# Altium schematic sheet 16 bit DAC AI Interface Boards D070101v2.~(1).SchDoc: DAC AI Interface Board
size B; Engineer: J. Heefner; DocumentNumber: D070101; Revision: 01; SheetNumber: 1; SheetTotal: 1; PageSetup: Record=PageOptions¦CenterHorizontal=True¦CenterVertical=True¦PrintScale=1.12¦XCorrection=1.00¦YCorrection=1.00¦PrintKind=0¦BorderSize=5000000¦LeftOffset=0¦BottomOffset=0¦Orientation=2¦PaperLength=1000¦PaperWidth=1000¦Scale=100¦PaperSource=15¦PrintQuality=1200¦MediaType=1¦DitherType=10¦PaperKind=Tabloid¦PrintScaleMode=1
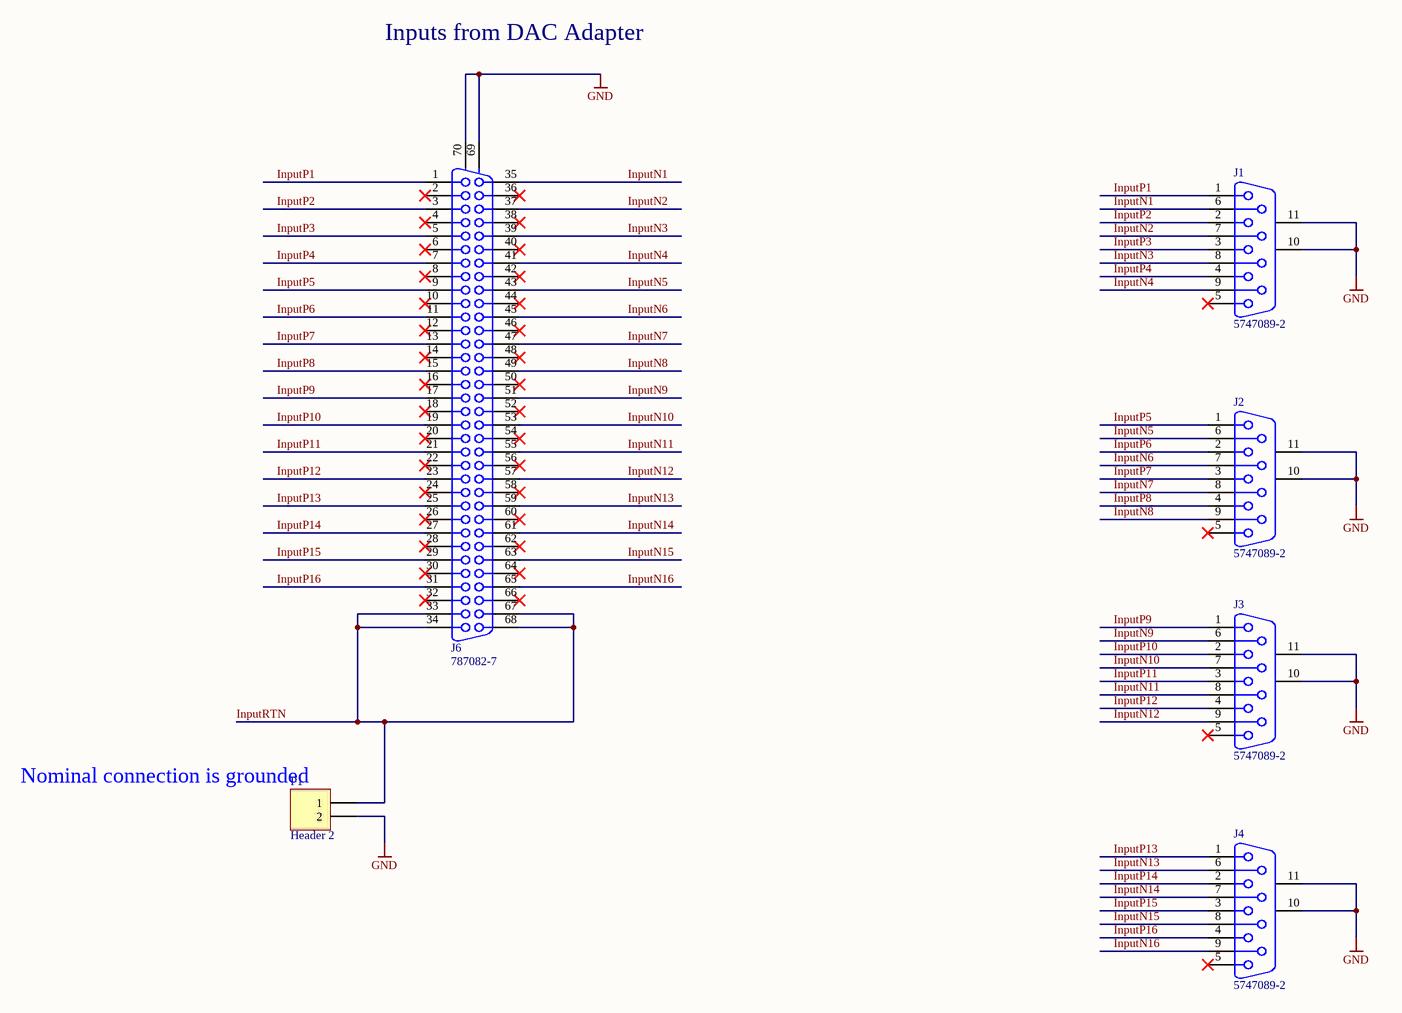
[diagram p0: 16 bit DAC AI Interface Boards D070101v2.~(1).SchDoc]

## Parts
J1  5747089-2  [DB9/F]
J2  5747089-2  [DB9/F]
J3  5747089-2  [DB9/F]
J4  5747089-2  [DB9/F]
J6  787082-7  [787082-7]
P1  Header 2  [HDR1X2]

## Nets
GND: J1.10(MH1) J1.11(MH2) J2.10(MH1) J2.11(MH2) J3.10(MH1) J3.11(MH2) J4.10(MH1) J4.11(MH2) J6.69(MH1) J6.70(MH2) P1.2
InputN1: J1.6 J6.35
InputN2: J1.7 J6.37
InputN3: J1.8 J6.39
InputN4: J1.9 J6.41
InputN5: J2.6 J6.43
InputN6: J2.7 J6.45
InputN7: J2.8 J6.47
InputN8: J2.9 J6.49
InputN9: J3.6 J6.51
InputN10: J3.7 J6.53
InputN11: J3.8 J6.55
InputN12: J3.9 J6.57
InputN13: J4.6 J6.59
InputN14: J4.7 J6.61
InputN15: J4.8 J6.63
InputN16: J4.9 J6.65
InputP1: J1.1 J6.1
InputP2: J1.2 J6.3
InputP3: J1.3 J6.5
InputP4: J1.4 J6.7
InputP5: J2.1 J6.9
InputP6: J2.2 J6.11
InputP7: J2.3 J6.13
InputP8: J2.4 J6.15
InputP9: J3.1 J6.17
InputP10: J3.2 J6.19
InputP11: J3.3 J6.21
InputP12: J3.4 J6.23
InputP13: J4.1 J6.25
InputP14: J4.2 J6.27
InputP15: J4.3 J6.29
InputP16: J4.4 J6.31
InputRTN: J6.33 J6.34 J6.67 J6.68 P1.1

Not connected (* = marked no-connect by the designer): J1 5*; J2 5*; J3 5*; J4 5*; J6 2* 4* 6* 8* 10* 12* 14* 16* 18* 20* 22* 24* 26* 28* 30* 32* 36* 38* 40* 42* 44* 46* 48* 50* 52* 54* 56* 58* 60* 62* 64* 66*

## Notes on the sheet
- Inputs from DAC Adapter
- (near P1) Nominal connection is grounded

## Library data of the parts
J1-J4 = 788750-1: Receptacle Assembly, 9 Position, Right Angle, 8.08mm Series, Amplimite; Manufacturer: TE Connectivity; Manufacturer Part Number: 5747844-4; Gender: Female; Description: D Sub Connector, Amplimite Hd-20, Amplimite Hd-20 Series, De, Receptacle, 9, Metal, Solder; Plating: Tin; Body Material: Metal; Voltage Rating: 125V; Current Rating: 6A; Number of Positions: 9; Number of Ports: 1; Mating Connector Lock: Yes (With); Preloaded: Yes; PCB Mount Retention: With; Sealable: No (Without); Pitch: 0.108inch; PCB Thickness: 1.58mm; Contact Post Length: 0.125inch; Hole Diameter: 3.18mm; Approvals: UL,CSA
J6 = 787082-7: Receptacle Assembly, Shielded, Right Angle, AMPLIMITE; Manufacturer: TE Connectivity; Gender: Female; Description: CONN D-TYPE RCPT 68POS R/A SLDR; Plating: Bright,Copper; Voltage Rating: 30V; Current Rating: 1A; Number of Positions: 68; Connector Type: Receptacle,Connector; Number of Ports: 1; Mating Alignment: No (Without); Mating Connector Lock: Yes (With); PCB Mount Retention: With; Pitch: 0.05inch; PCB Thickness: 1.57mm; Contact Post Length: 0.1inch; Hole Diameter: 0.109inch; Approvals: UL
P1 = Header 2: Header, 2-Pin; Manufacturer: Molex; Description: Wire-To-Board Connector, KK 6373 Series, Through Hole, Header, 2, 2.54 mm, Tin Plated Contacts; Number of Positions: 2; Gender: Male; Contact Resistance: 10mR; Max Current Rating: 4A; Voltage Rating: 250V; Insulation Resistance: 500GR; Pitch: 2.54mm; Approvals: UL,CSA; Glow Wire Compliant: Non-compliant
